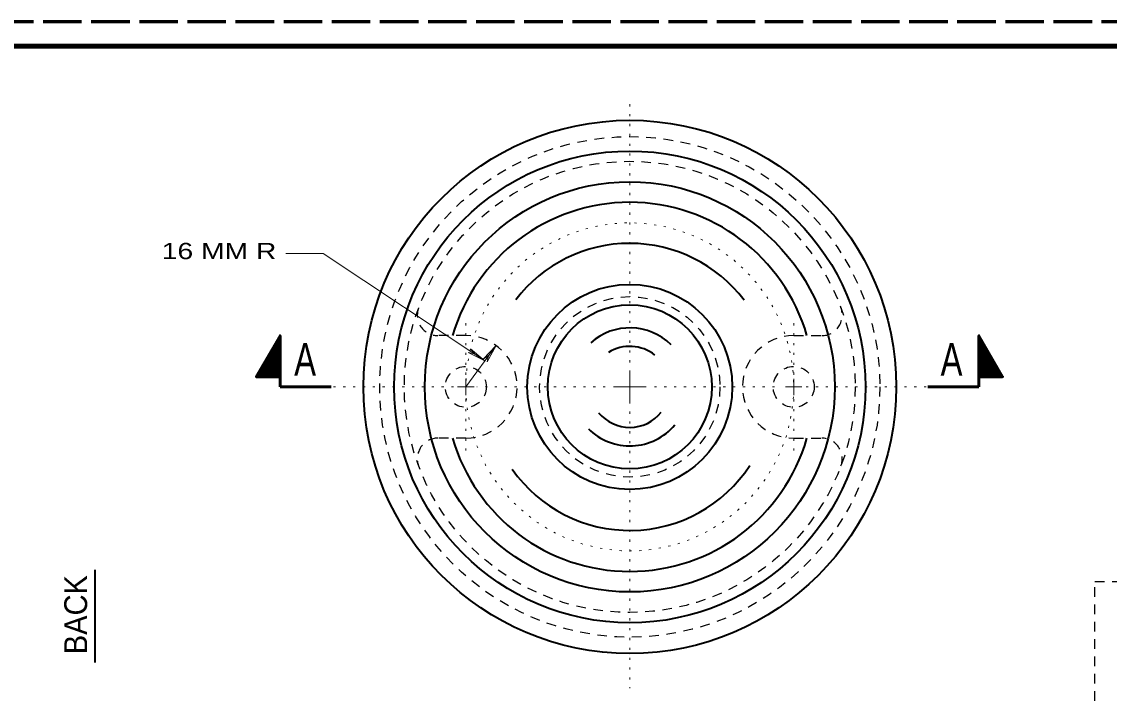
# Model space of a CAD drawing. Extents: x 312583 to 312853, y 144419 to 144586.
# Drawn here: x 312718.5 to 312769.3, y 144554.6 to 144586.2 of the extents above; entities that cross this region are included whole.
import ezdxf
from ezdxf.enums import TextEntityAlignment as Align

# ---------------------------------------------------------------- set-up
doc = ezdxf.new("R2010")
doc.units = 0
doc.header["$LTSCALE"] = 0.3
for name, pattern in [('DOTTED', [1.5, 0.3, -1.2]), ('LONG_DASHED', [7.5, 6, -1.5]), ('SHORT_DASHED', [2.7, 1.5, -1.2])]:
    doc.linetypes.add(name, pattern=pattern)
doc.layers.add('1', color=7, linetype='Continuous', lineweight=13)

msp = doc.modelspace()

# ---------------------------------------------------------------- linework, layer by layer
at = {"layer": '1', "linetype": 'LONG_DASHED', "lineweight": 60}
msp.add_line((312851.75, 144586.2246), (312583.526, 144586.2246), dxfattribs=at)
msp.add_line((312851.75, 144586.2246), (312583.526, 144586.2246), dxfattribs=at)
at = {"layer": '1', "linetype": 'DOTTED'}
for p, q in [((312746.8851, 144570.3077), (312746.8851, 144582.6281)), ((312739.2185, 144569.7327), (312739.2185, 144572.4697)), ((312754.5518, 144569.7327), (312754.5518, 144572.3777)), ((312738.6435, 144569.1577), (312732.9241, 144569.1577)), ((312745.7351, 144569.1577), (312739.7245, 144569.1577)), ((312748.0351, 144569.1577), (312753.9155, 144569.1577)), ((312755.1268, 144569.1577), (312760.8155, 144569.1577)), ((312739.2185, 144568.5827), (312739.2185, 144565.9837)), ((312754.5518, 144568.5827), (312754.5518, 144565.9531)), ((312746.8851, 144568.0077), (312746.8851, 144555.0817))]:
    msp.add_line(p, q, dxfattribs=at)
at = {"layer": '1', "lineweight": 35}
for p, q in [((312730.5321, 144571.5037), (312730.5091, 144571.5114)), ((312730.5321, 144571.5344), (312730.5168, 144571.5344)), ((312763.2075, 144571.5344), (312763.2228, 144571.5344)), ((312763.2075, 144571.5037), (312763.2305, 144571.5114)), ((312730.5321, 144570.8137), (312730.2101, 144570.9977)), ((312730.5321, 144570.8367), (312730.2255, 144571.0131)), ((312730.5321, 144570.8674), (312730.2331, 144571.0361)), ((312730.5321, 144570.8981), (312730.2485, 144571.0591)), ((312730.5321, 144570.9211), (312730.2561, 144571.0744)), ((312730.5321, 144570.9517), (312730.2715, 144571.1051)), ((312730.5321, 144570.9747), (312730.2791, 144571.1204)), ((312730.5321, 144571.0054), (312730.2945, 144571.1434)), ((312730.5321, 144571.0361), (312730.3021, 144571.1664)), ((312730.5321, 144571.0591), (312730.3175, 144571.1817)), ((312730.5321, 144571.0897), (312730.3251, 144571.2047)), ((312730.5321, 144571.1127), (312730.3405, 144571.2277)), ((312730.5321, 144571.1434), (312730.3558, 144571.2431)), ((312730.5321, 144571.1741), (312730.3635, 144571.2661)), ((312730.5321, 144571.2047), (312730.3788, 144571.2891)), ((312730.5321, 144571.2277), (312730.3941, 144571.3044)), ((312730.5321, 144571.2584), (312730.4018, 144571.3274)), ((312730.5321, 144571.2814), (312730.4171, 144571.3504)), ((312730.5321, 144571.3044), (312730.4248, 144571.3734)), ((312730.5321, 144571.3351), (312730.4401, 144571.3887)), ((312730.5321, 144571.3657), (312730.4478, 144571.4117)), ((312730.5321, 144571.3964), (312730.4631, 144571.4347)), ((312730.5321, 144571.4194), (312730.4708, 144571.4501)), ((312730.5321, 144571.4501), (312730.4861, 144571.4731)), ((312730.5321, 144571.4731), (312730.4938, 144571.4961)), ((312763.2075, 144571.4731), (312763.2458, 144571.4961)), ((312763.2075, 144571.4501), (312763.2535, 144571.4731)), ((312763.2075, 144571.4194), (312763.2688, 144571.4501)), ((312763.2075, 144571.3964), (312763.2765, 144571.4347)), ((312763.2075, 144571.3657), (312763.2918, 144571.4117)), ((312763.2075, 144571.3351), (312763.2995, 144571.3887)), ((312763.2075, 144571.3044), (312763.3148, 144571.3734)), ((312763.2075, 144571.2814), (312763.3225, 144571.3504)), ((312763.2075, 144571.2584), (312763.3378, 144571.3274)), ((312763.2075, 144571.2277), (312763.3455, 144571.3044)), ((312763.2075, 144571.2047), (312763.3608, 144571.2891)), ((312763.2075, 144571.1741), (312763.3761, 144571.2661)), ((312763.2075, 144571.1434), (312763.3838, 144571.2431)), ((312763.2075, 144571.1127), (312763.3991, 144571.2277)), ((312763.2075, 144571.0897), (312763.4145, 144571.2047)), ((312763.2075, 144571.0591), (312763.4221, 144571.1817)), ((312763.2075, 144571.0361), (312763.4375, 144571.1664)), ((312763.2075, 144571.0054), (312763.4451, 144571.1434)), ((312763.2075, 144570.9747), (312763.4605, 144571.1204)), ((312763.2075, 144570.9517), (312763.4681, 144571.1051)), ((312763.2075, 144570.9211), (312763.4835, 144571.0744)), ((312763.2075, 144570.8981), (312763.4911, 144571.0591)), ((312763.2075, 144570.8674), (312763.5065, 144571.0361)), ((312763.2075, 144570.8367), (312763.5141, 144571.0131)), ((312763.2075, 144570.8137), (312763.5295, 144570.9977)), ((312730.5321, 144570.1467), (312729.9265, 144570.4994)), ((312730.5321, 144570.1774), (312729.9341, 144570.5147)), ((312730.5321, 144570.2081), (312729.9495, 144570.5377)), ((312730.5321, 144570.2311), (312729.9571, 144570.5607)), ((312730.5321, 144570.2617), (312729.9725, 144570.5761)), ((312730.5245, 144570.2847), (312729.9801, 144570.6067)), ((312730.5321, 144570.3154), (312729.9955, 144570.6221)), ((312730.5321, 144570.3384), (312730.0108, 144570.6451)), ((312730.5321, 144570.3691), (312730.0185, 144570.6681)), ((312730.5321, 144570.3997), (312730.0338, 144570.6834)), ((312730.5321, 144570.4227), (312730.0415, 144570.7064)), ((312730.5321, 144570.4534), (312730.0568, 144570.7294)), ((312730.5321, 144570.4841), (312730.0645, 144570.7447)), ((312730.5321, 144570.5071), (312730.0798, 144570.7677)), ((312730.5321, 144570.5377), (312730.0875, 144570.7907)), ((312730.5321, 144570.5684), (312730.1028, 144570.8061)), ((312730.5321, 144570.5914), (312730.1105, 144570.8291)), ((312730.5321, 144570.6144), (312730.1258, 144570.8521)), ((312730.5321, 144570.6451), (312730.1335, 144570.8751)), ((312730.5321, 144570.6757), (312730.1488, 144570.8904)), ((312730.5321, 144570.7064), (312730.1641, 144570.9134)), ((312730.5321, 144570.7294), (312730.1718, 144570.9364)), ((312730.5321, 144570.7601), (312730.1871, 144570.9517)), ((312730.5321, 144570.7831), (312730.2025, 144570.9747)), ((312763.2075, 144570.7831), (312763.5371, 144570.9747)), ((312763.2075, 144570.7601), (312763.5525, 144570.9517)), ((312763.2075, 144570.7294), (312763.5678, 144570.9364)), ((312763.2075, 144570.7064), (312763.5755, 144570.9134)), ((312763.2075, 144570.6757), (312763.5908, 144570.8904)), ((312763.2075, 144570.6451), (312763.6061, 144570.8751)), ((312763.2075, 144570.6144), (312763.6138, 144570.8521)), ((312763.2075, 144570.5914), (312763.6291, 144570.8291)), ((312763.2075, 144570.5684), (312763.6368, 144570.8061)), ((312763.2075, 144570.5377), (312763.6521, 144570.7907)), ((312763.2075, 144570.5071), (312763.6598, 144570.7677)), ((312763.2075, 144570.4841), (312763.6751, 144570.7447)), ((312763.2075, 144570.4534), (312763.6828, 144570.7294)), ((312763.2075, 144570.4227), (312763.6981, 144570.7064)), ((312763.2075, 144570.3997), (312763.7058, 144570.6834)), ((312763.2075, 144570.3691), (312763.7211, 144570.6681)), ((312763.2075, 144570.3384), (312763.7288, 144570.6451)), ((312763.2075, 144570.3154), (312763.7441, 144570.6221)), ((312763.2075, 144570.2617), (312763.7671, 144570.5761)), ((312763.2075, 144570.2311), (312763.7825, 144570.5607)), ((312763.2075, 144570.2081), (312763.7901, 144570.5377)), ((312763.2075, 144570.1774), (312763.8055, 144570.5147)), ((312763.2075, 144570.1467), (312763.8131, 144570.4994)), ((312763.2151, 144570.2847), (312763.7595, 144570.6067)), ((312730.2255, 144569.6331), (312729.6275, 144569.9781)), ((312730.2715, 144569.6331), (312729.6351, 144570.0011)), ((312730.3175, 144569.6331), (312729.6505, 144570.0164)), ((312730.3635, 144569.6331), (312729.6658, 144570.0394)), ((312730.4171, 144569.6331), (312729.6735, 144570.0624)), ((312730.4555, 144569.6331), (312729.6888, 144570.0777)), ((312730.5091, 144569.6331), (312729.6965, 144570.1084)), ((312730.5321, 144569.6484), (312729.7118, 144570.1237)), ((312730.5321, 144569.6791), (312729.7195, 144570.1467)), ((312730.5321, 144569.7097), (312729.7348, 144570.1697)), ((312730.5321, 144569.7327), (312729.7425, 144570.1851)), ((312730.5321, 144569.7634), (312729.7578, 144570.2081)), ((312730.5245, 144569.7864), (312729.7655, 144570.2311)), ((312730.5245, 144569.8171), (312729.7808, 144570.2464)), ((312730.5321, 144569.8401), (312729.7885, 144570.2694)), ((312730.5321, 144569.8707), (312729.8038, 144570.2924)), ((312730.5321, 144569.9014), (312729.8191, 144570.3077)), ((312730.5321, 144569.9244), (312729.8268, 144570.3307)), ((312730.5321, 144569.9551), (312729.8421, 144570.3537)), ((312730.5321, 144569.9857), (312729.8575, 144570.3767)), ((312730.5321, 144570.0087), (312729.8651, 144570.3921)), ((312730.5245, 144570.0394), (312729.8805, 144570.4151)), ((312730.5321, 144570.0701), (312729.8881, 144570.4381)), ((312730.5321, 144570.0931), (312729.9035, 144570.4534)), ((312730.5321, 144570.1161), (312729.9111, 144570.4764)), ((312763.2075, 144570.1161), (312763.8285, 144570.4764)), ((312763.2075, 144570.0931), (312763.8361, 144570.4534)), ((312763.2075, 144570.0701), (312763.8515, 144570.4381)), ((312763.2075, 144570.0087), (312763.8745, 144570.3921)), ((312763.2075, 144569.9857), (312763.8821, 144570.3767)), ((312763.2075, 144569.9551), (312763.8975, 144570.3537)), ((312763.2075, 144569.9244), (312763.9128, 144570.3307)), ((312763.2075, 144569.9014), (312763.9205, 144570.3077)), ((312763.2075, 144569.8707), (312763.9358, 144570.2924)), ((312763.2075, 144569.8401), (312763.9511, 144570.2694)), ((312763.2075, 144569.7634), (312763.9818, 144570.2081)), ((312763.2075, 144569.7327), (312763.9971, 144570.1851)), ((312763.2075, 144569.7097), (312764.0048, 144570.1697)), ((312763.2075, 144569.6791), (312764.0201, 144570.1467)), ((312763.2075, 144569.6484), (312764.0278, 144570.1237)), ((312763.2151, 144570.0394), (312763.8591, 144570.4151)), ((312763.2151, 144569.8171), (312763.9588, 144570.2464)), ((312763.2151, 144569.7864), (312763.9741, 144570.2311)), ((312763.2305, 144569.6331), (312764.0431, 144570.1084)), ((312763.2841, 144569.6331), (312764.0508, 144570.0777)), ((312763.3225, 144569.6331), (312764.0661, 144570.0624)), ((312763.3761, 144569.6331), (312764.0738, 144570.0394)), ((312763.4221, 144569.6331), (312764.0891, 144570.0164)), ((312763.4681, 144569.6331), (312764.1045, 144570.0011)), ((312763.5141, 144569.6331), (312764.1121, 144569.9781)), ((312729.4511, 144569.6331), (312729.4358, 144569.6484)), ((312729.4971, 144569.6331), (312729.4435, 144569.6714)), ((312729.5508, 144569.6331), (312729.4588, 144569.6867)), ((312729.5968, 144569.6331), (312729.4741, 144569.7097)), ((312729.6505, 144569.6331), (312729.4818, 144569.7327)), ((312729.6888, 144569.6331), (312729.4971, 144569.7481)), ((312729.7425, 144569.6331), (312729.5048, 144569.7711)), ((312729.7885, 144569.6331), (312729.5201, 144569.7941)), ((312729.8345, 144569.6331), (312729.5278, 144569.8094)), ((312729.8805, 144569.6331), (312729.5431, 144569.8401)), ((312729.9341, 144569.6331), (312729.5508, 144569.8554)), ((312729.9801, 144569.6331), (312729.5661, 144569.8784)), ((312730.0261, 144569.6331), (312729.5738, 144569.9014)), ((312730.0798, 144569.6331), (312729.5891, 144569.9167)), ((312730.1258, 144569.6331), (312729.5968, 144569.9397)), ((312730.1718, 144569.6331), (312729.6121, 144569.9551)), ((312763.5678, 144569.6331), (312764.1275, 144569.9551)), ((312763.6138, 144569.6331), (312764.1428, 144569.9397)), ((312763.6598, 144569.6331), (312764.1505, 144569.9167)), ((312763.7135, 144569.6331), (312764.1658, 144569.9014)), ((312763.7595, 144569.6331), (312764.1735, 144569.8784)), ((312763.8055, 144569.6331), (312764.1888, 144569.8554)), ((312763.8591, 144569.6331), (312764.1965, 144569.8401)), ((312763.9051, 144569.6331), (312764.2118, 144569.8094)), ((312763.9511, 144569.6331), (312764.2195, 144569.7941)), ((312763.9971, 144569.6331), (312764.2348, 144569.7711)), ((312764.0508, 144569.6331), (312764.2425, 144569.7481)), ((312764.0891, 144569.6331), (312764.2578, 144569.7327)), ((312764.1428, 144569.6331), (312764.2655, 144569.7097)), ((312764.1888, 144569.6331), (312764.2808, 144569.6867)), ((312764.2425, 144569.6331), (312764.2961, 144569.6714)), ((312764.2885, 144569.6331), (312764.3038, 144569.6484)), ((312721.879, 144556.2839), (312721.879, 144560.6079))]:
    msp.add_line(p, q, dxfattribs=at)
at = {"layer": '1', "linetype": 'SHORT_DASHED', "lineweight": 25}
for p, q in [((312739.2185, 144571.5574), (312737.9075, 144571.5574)), ((312754.5518, 144571.5574), (312755.8628, 144571.5574)), ((312739.2185, 144566.7657), (312737.9075, 144566.7657)), ((312754.5518, 144566.7657), (312755.8628, 144566.7657)), ((312768.638, 144560.0713), (312839.5547, 144560.0713)), ((312768.638, 144508.3213), (312768.638, 144560.0713))]:
    msp.add_line(p, q, dxfattribs=at)
at = {"layer": '1'}
for p, q in [((312739.2185, 144569.1577), (312740.6291, 144571.0974)), ((312740.6291, 144571.0974), (312740.0311, 144570.4611)), ((312740.6291, 144571.0974), (312740.2075, 144570.3384)), ((312739.3258, 144570.7677), (312739.6171, 144570.7064)), ((312740.1078, 144570.3767), (312739.3258, 144570.7677)), ((312739.4408, 144570.9441), (312739.6171, 144570.7064)), ((312740.1078, 144570.3767), (312739.4408, 144570.9441)), ((312740.0311, 144570.4611), (312740.2841, 144570.6221)), ((312740.2075, 144570.3384), (312740.2841, 144570.6221)), ((312739.2185, 144569.1577), (312739.2185, 144569.5411)), ((312746.8851, 144569.1577), (312746.8851, 144569.9244)), ((312754.5518, 144569.1577), (312754.5518, 144569.5411)), ((312739.2185, 144569.1577), (312738.8351, 144569.1577)), ((312739.2185, 144569.1577), (312739.6018, 144569.1577)), ((312739.2185, 144569.1577), (312739.2185, 144568.7744)), ((312746.8851, 144569.1577), (312746.1185, 144569.1577)), ((312746.8851, 144569.1577), (312747.6518, 144569.1577)), ((312746.8851, 144569.1577), (312746.8851, 144568.3911)), ((312754.5518, 144569.1577), (312754.1685, 144569.1577)), ((312754.5518, 144569.1577), (312754.9351, 144569.1577)), ((312754.5518, 144569.1577), (312754.5518, 144568.7744))]:
    msp.add_line(p, q, dxfattribs=at)
at = {"layer": '1', "lineweight": 53}
for p, q in [((312730.5321, 144569.6331), (312730.5321, 144569.1577)), ((312763.2075, 144569.6331), (312763.2075, 144569.1577)), ((312732.9241, 144569.1577), (312730.5321, 144569.1577)), ((312760.8155, 144569.1577), (312763.2075, 144569.1577))]:
    msp.add_line(p, q, dxfattribs=at)
at = {"layer": '1', "lineweight": 158}
msp.add_lwpolyline([(312616.5, 144423.1446), (312616.5, 144585.0846), (312849, 144585.0846)], dxfattribs=at)
at = {"layer": '1'}
msp.add_lwpolyline([(312740.1078, 144570.3767), (312732.5485, 144575.3984), (312730.8005, 144575.3984)], dxfattribs=at)
at = {"layer": '1', "lineweight": 53}
for points in [[(312730.5321, 144569.6331), (312729.4205, 144569.6331), (312730.5321, 144571.5497)], [(312763.2075, 144569.6331), (312764.3191, 144569.6331), (312763.2075, 144571.5497)]]:
    msp.add_lwpolyline(points, close=True, dxfattribs=at)
at = {"layer": '1', "lineweight": 40}
for radius in [12.4583, 11.0208, 9.5833, 4.7917, 3.8333]:
    msp.add_circle((312746.8851, 144569.1616), radius, dxfattribs=at)
at = {"layer": '1', "linetype": 'SHORT_DASHED', "lineweight": 25}
for centre, radius in [((312746.8851, 144569.1616), 11.6955), ((312746.8851, 144569.1616), 10.5417), ((312746.8851, 144569.1616), 4.2167), ((312739.2185, 144569.1616), 0.9583), ((312754.5518, 144569.1616), 0.9583)]:
    msp.add_circle(centre, radius, dxfattribs=at)
at = {"layer": '1', "linetype": 'DOTTED'}
msp.add_circle((312746.8851, 144569.1616), 7.6667, dxfattribs=at)
at = {"layer": '1', "lineweight": 40}
for radius, start, end in [(8.625, 16.12762, 163.86918), (6.7083, 37.2286, 142.63286), (2.7568, 45.50703, 131.50106), (1.8925, 51.63616, 121.91926), (1.8925, 219.65694, 321.18094), (2.7568, 225.38233, 319.79641), (8.625, 196.12762, 343.86918), (6.7083, 215.00759, 326.84244)]:
    msp.add_arc((312746.8851, 144569.1616), radius, start, end, dxfattribs=at)
at = {"layer": '1', "linetype": 'SHORT_DASHED', "lineweight": 25}
for centre, radius, start, end in [((312737.9079, 144572.5157), 0.9583, 159.51269, 270), ((312755.8623, 144572.5157), 0.9583, 270, 20.48731), ((312739.2185, 144569.1616), 2.3958, 270, 90), ((312754.5518, 144569.1616), 2.3958, 90, 270), ((312737.9079, 144565.8074), 0.9583, 90, 200.48731), ((312755.8623, 144565.8074), 0.9583, 339.51269, 90)]:
    msp.add_arc(centre, radius, start, end, dxfattribs=at)

# ---------------------------------------------------------------- texts
at = {"layer": '1', "width": 1.3}
msp.add_text(' 16 MM R', height=0.76, dxfattribs=at).set_placement((312724.63, 144575.1307))
at = {"layer": '1', "width": 0.75}
for p in [(312731.7013, 144569.6791), (312761.931, 144569.6791)]:
    msp.add_text('A', height=1.533, dxfattribs=at).set_placement(p, align=Align.CENTER)
at = {"layer": '1', "width": 0.95}
msp.add_text('BACK', height=1.07, rotation=90, dxfattribs=at).set_placement((312721.509, 144558.5184), align=Align.CENTER)

doc.saveas('drawing.dxf')
